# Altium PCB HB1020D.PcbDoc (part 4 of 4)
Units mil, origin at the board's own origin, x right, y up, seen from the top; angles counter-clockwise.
Board outline 4729.44 x 3075.9 mil, 2 copper layers (Top Layer, Bottom Layer); 113 components, 129 nets, 454 pads, 503 vias.
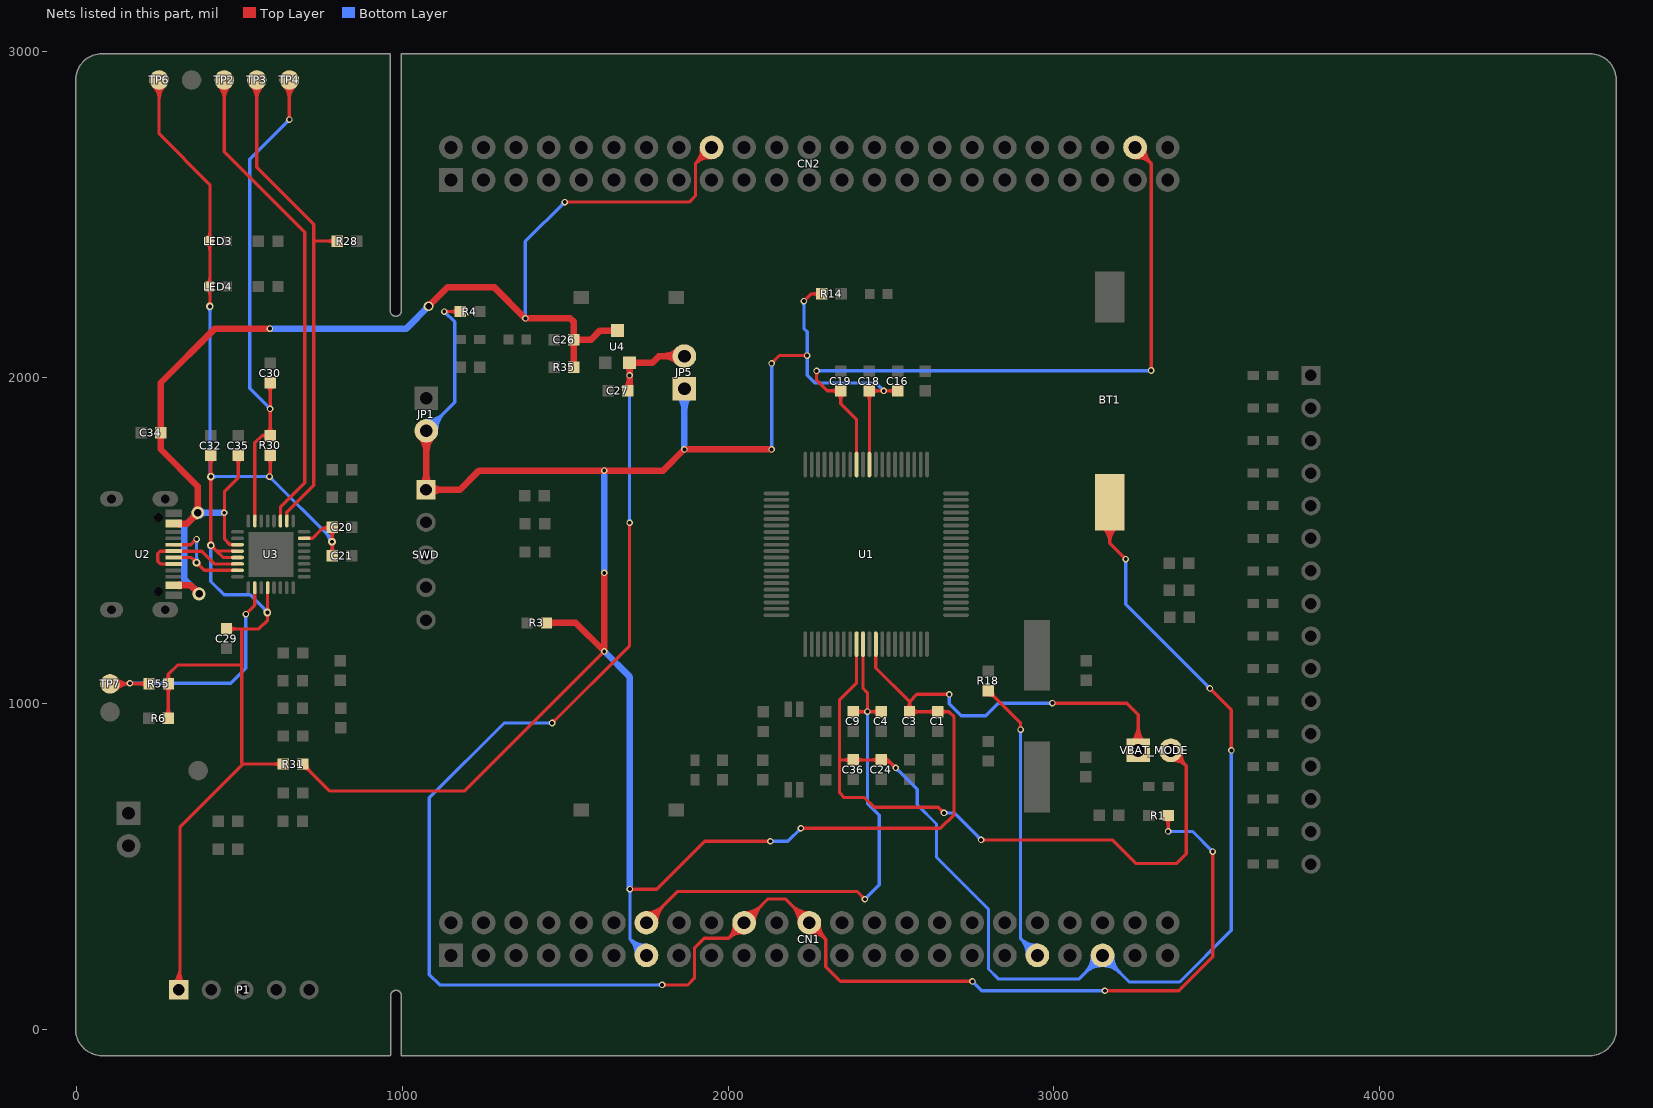
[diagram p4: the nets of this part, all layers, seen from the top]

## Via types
v1: diameter 20, hole 12, Top Layer to Bottom Layer, tented both sides, 475 vias
v2: diameter 23.62, hole 11.81, Top Layer to Bottom Layer, tented both sides, 20 vias
v3: diameter 122.05, hole 122.05, Top Layer to Bottom Layer, tented both sides, 4 vias
v4: diameter 39.37, hole 23.62, Top Layer to Bottom Layer, tented both sides, 2 vias
v5: diameter 30, hole 20, Top Layer to Bottom Layer, tented both sides, 1 vias
v6: diameter 15, hole 8, Top Layer to Bottom Layer, tented both sides, 1 vias

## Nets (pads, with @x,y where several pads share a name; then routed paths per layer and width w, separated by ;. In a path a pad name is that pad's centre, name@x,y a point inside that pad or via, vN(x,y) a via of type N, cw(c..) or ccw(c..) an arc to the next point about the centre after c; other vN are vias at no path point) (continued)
PF1: CN1.37 R18.2 | length 1152.3
  Top Layer w10: R18.2@2798.61,1026.81 cw(c2798.61,996.63) 2819.95,1017.97 cw(c2841.28,1039.31) R18.2@2811.11,1039.31 ; R18.2@2798.61,1039.31 2898,939.91 v1(2898,919.81) ; v1@2894.46,923.35 ccw(c2885.93,931.88) 2898,931.88 ccw(c2910.07,931.88) v1@2901.54,923.35
  Bottom Layer w10: v1@2894.46,916.28 cw(c2885.93,907.74) 2898,907.74 cw(c2910.07,907.74) v1@2901.54,916.28 ; v1@2900.19,922 v1(2898,919.81) 2898,278.39 ; CN1.37@2918.2,227.66 ccw(c2849.18,229.57) 2898,278.39 ; CN1.37@2928.2,227.38 ccw(c2881.14,228.68) 2914.43,261.97 ccw(c2947.71,295.25) CN1.37@2949.01,248.2 ; CN1.37@2948.74,258.19 cw(c2946.83,327.22) 2898,278.39 ; CN1.37@2949.61,226.79 2898,278.39
PF2: C19.2 CN2.44 U1.52 | length 2435.9
  Top Layer w10: v1@2268.46,2017.46 cw(c2259.93,2008.93) 2272,2008.93 cw(c2284.07,2008.93) v1@2275.54,2017.46 ; v1(2272,2021) 2272,1992 2304.21,1959.79 C19.2@2346.27,1959.79 2346.27,1919.73 2394.74,1871.26 U1.52@2394.74,1733.38 ; C19.2@2337.43,1968.63 cw(c2316.09,1989.97) 2316.09,1959.79 cw(c2316.09,1929.61) 2337.43,1950.95 cw(c2316.09,1929.61) 2346.27,1929.61 cw(c2376.44,1929.61) C19.2@2355.11,1950.95 ; CN2.44@3249.61,2706.79 3299.02,2657.37 ; CN2.44@3250.88,2685.41 cw(c3253.4,2643.21) 3283.29,2673.1 cw(c3313.19,2702.99) CN2.44@3270.99,2705.51 ; CN2.44@3251.48,2675.43 cw(c3255.17,2613.52) 3299.02,2657.37 ; CN2.44@3280.97,2704.92 ccw(c3342.87,2701.22) 3299.02,2657.37 ; v1@3295.49,2025.54 ccw(c3286.95,2034.08) 3299.02,2034.08 ccw(c3311.1,2034.08) v1@3302.56,2025.54 ; v1(3299.02,2022.01) 3299.02,2657.37
  Bottom Layer w10: v1(2272,2021) 2352,2021 3298.02,2021 v1(3299.02,2022.01) ; v1@2275.54,2017.46 cw(c2284.07,2008.93) 2284.07,2021 cw(c2284.07,2033.07) v1@2275.54,2024.54 ; 3284.52,2021 ccw(c3284.52,2036.51) v1@3295.49,2025.54
PRG_NRST: C30.1 R30.2 TP4.1 U3.7 | length 1920.5
  Top Layer w10: U3.7@547.39,1560.15 547.39,1800.09 569.61,1822.31 ; R30.2@584.61,1814.81 ccw(c569.61,1803.56) 569.61,1822.31 ; R30.2@584.61,1829.81 cw(c569.61,1841.05) 569.61,1822.31 ; R30.2@585.77,1831.14 ccw(c564.43,1852.48) 594.61,1852.48 ccw(c624.78,1852.48) R30.2@603.45,1831.14 ; C30.1@585.77,1975.47 cw(c564.43,1954.13) 594.61,1954.13 cw(c624.78,1954.13) C30.1@603.45,1975.47 ; v1@591.07,1900.77 cw(c582.54,1892.24) 594.61,1892.24 cw(c606.68,1892.24) v1@598.14,1900.77 ; v1@591.07,1907.84 ccw(c582.54,1916.38) 594.61,1916.38 ccw(c606.68,1916.38) v1@598.14,1907.84 ; C30.1@594.61,1984.31 v1(594.61,1904.31) R30.2@594.61,1822.31 569.61,1822.31 ; TP4.1@635.93,2896.11 cw(c593.25,2853.43) 653.61,2853.43 cw(c713.96,2853.43) TP4.1@671.28,2896.11 ; TP4.1@643,2903.18 cw(c617.39,2877.57) 653.61,2877.57 cw(c689.82,2877.57) TP4.1@664.21,2903.18 ; v1@650.07,2795.84 ccw(c641.54,2804.38) 653.61,2804.38 ccw(c665.68,2804.38) v1@657.14,2795.84 ; v1(653.61,2792.31) TP4.1@653.61,2913.79
  Bottom Layer w10: v1@589.61,1904.31 ccw(c577.54,1904.31) 586.07,1912.84 ccw(c594.61,1921.38) v1@594.61,1909.31 ; v1(594.61,1904.31) 531.61,1967.31 531.61,2670.31 v1(653.61,2792.31) ; v1@648.61,2792.31 cw(c636.54,2792.31) 645.07,2783.77 cw(c653.61,2775.24) v1@653.61,2787.31
PRG_SWCLK: R28.2 TP3.1 U3.2 | length 1731.5
  Top Layer w10: TP3.1@535.93,2896.11 cw(c493.25,2853.43) 553.61,2853.43 cw(c613.96,2853.43) TP3.1@571.28,2896.11 ; TP3.1@543,2903.18 cw(c517.39,2877.57) 553.61,2877.57 cw(c589.82,2877.57) TP3.1@564.21,2903.18 ; TP3.1@553.61,2913.79 553.61,2645.31 728.61,2470.31 728.61,1669.31 645.82,1586.52 U3.2@645.82,1560.15 ; 728.61,2419.31 R28.2@800.61,2419.31 ; R28.2@791.77,2410.47 ccw(c770.43,2389.13) 770.43,2419.31 ccw(c770.43,2449.49) R28.2@791.77,2428.15
PRG_SWDIO: TP2.1 U3.3 | length 1640.5
  Top Layer w10: TP2.1@435.93,2896.11 cw(c393.25,2853.43) 453.61,2853.43 cw(c513.96,2853.43) TP2.1@471.28,2896.11 ; TP2.1@443,2903.18 cw(c417.39,2877.57) 453.61,2877.57 cw(c489.82,2877.57) TP2.1@464.21,2903.18 ; TP2.1@453.61,2913.79 453.61,2693.31 700.61,2446.31 700.61,1677.31 626.13,1602.83 U3.3@626.13,1560.15 U3.3@626.13,1558.18
UPDATE_CTRL: R55.2 TP7.1 U3.18 | length 1036.9
  Top Layer w10: TP7.1@103.35,1060.31 R55.2@222.61,1060.31 ; TP7.1@113.65,1049.39 cw(c140,1023.04) 140,1060.31 ; TP7.1@113.65,1070.61 ccw(c138.51,1095.47) 138.51,1060.31 ; TP7.1@120.72,1042.32 cw(c164.14,998.9) v1@164.14,1060.31 ; TP7.1@120.72,1077.68 ccw(c162.65,1119.61) v1@162.65,1060.31 ; 147.84,1060.31 ccw(c147.84,1078.16) v1@160.46,1065.54 ; v1@167.54,1065.54 ccw(c180.16,1078.16) 180.16,1060.31 ; R55.2@213.77,1051.47 ccw(c192.43,1030.13) 192.43,1060.31 ccw(c192.43,1090.49) R55.2@213.77,1069.15 ; v1(520,1274) 547.39,1301.39 U3.18@547.39,1355.43 ; v1@520,1279 ccw(c520,1291.07) 528.54,1282.54 ccw(c537.07,1274) v1@525,1274
  Bottom Layer w10: v1(164,1062) 473.61,1062 520,1108.39 v1(520,1274) ; v1@167.54,1058.46 cw(c176.07,1049.93) 176.07,1062 cw(c176.07,1074.07) v1@167.54,1065.54 ; v1@516.46,1270.46 cw(c507.93,1261.93) 520,1261.93 cw(c532.07,1261.93) v1@523.54,1270.46
USB_DM: U2.A7 U2.B7 U3.15 | length 479.4
  Top Layer w10: U2.A7@298.2,1447.87 353.04,1447.87 392.34,1408.57 U3.15@494.24,1408.57 U3.15@496.21,1408.57 ; U2.B7@298.2,1487.24 351.54,1487.24 v1(368.61,1504.31) ; v2@361.93,1432.17 ccw(c345.49,1432.17) 357.12,1443.8 ccw(c368.74,1455.42) v2@368.74,1438.98 ; v1@363.61,1504.31 cw(c351.54,1504.31) 360.07,1495.77 cw(c368.61,1487.24) v1@368.61,1499.31 ; v2@368.74,1425.36 cw(c368.74,1408.92) 380.37,1420.54 cw(c392,1432.17) v2@375.56,1432.17
  Bottom Layer w10: v2@363.93,1436.99 ccw(c352.3,1448.61) 368.74,1448.61 ccw(c385.19,1448.61) v2@373.56,1436.99 ; v1@365.07,1500.77 cw(c356.2,1491.9) 368.74,1491.9 ; v1(368.61,1504.31) 368.74,1504.17 v2(368.74,1432.17) ; 368.74,1492.57 cw(c380.34,1492.57) v1@372.14,1500.77
USB_DP: U2.A6 U2.B6 U3.14 | length 341.8
  Top Layer w10: U2.B6@298.2,1428.18 257.73,1428.18 249.61,1436.31 249.61,1460.31 256.85,1467.55 U2.A6@298.2,1467.55 384.36,1467.55 384.61,1467.31 423.65,1428.26 U3.14@494.24,1428.26 U3.14@496.21,1428.26
VBAT: BT1.1 C24.2 C36.2 CN1.41 U1.9 VBAT_MODE.2 | length 6533.9
  Top Layer w10: 2342.69,826.79 C36.2@2384.6,826.79 C24.2@2470.93,826.79 2490.21,826.79 ; C36.2@2375.76,817.95 ccw(c2354.42,796.61) 2354.42,826.79 ccw(c2354.42,856.96) C36.2@2375.76,835.62 ; C36.2@2393.44,817.95 cw(c2414.78,796.61) 2414.78,826.79 cw(c2414.78,856.96) C36.2@2393.44,835.62 ; U1.9@2394.74,1182.2 2394.74,1063.74 2342.48,1011.48 2342.48,725.52 2357,711 2419,711 2449,681 2646,681 v1(2663,664) ; C24.2@2462.1,817.95 ccw(c2440.76,796.61) 2440.76,826.79 ccw(c2440.76,856.96) C24.2@2462.1,835.62 ; C24.2@2470.87,834.29 cw(c2471.11,806.28) 2490.91,826.09 ; C24.2@2470.96,824.29 cw(c2471.41,772.86) 2507.78,809.22 ; C24.2@2472.63,824.94 cw(c2482.33,814.38) 2492.48,824.52 ; C24.2@2479.39,817.58 cw(c2489.4,806.69) 2499.85,817.15 ; C24.2@2482.35,821.69 cw(c2490.21,818.17) 2490.21,826.79 ; C24.2@2482.35,831.89 ccw(c2490.21,835.4) 2490.21,826.79 ; v1@2510,802 ccw(c2497.93,802) 2506.46,810.54 ccw(c2515,819.07) v1@2515,807 ; v1(2515,802) 2490.21,826.79 ; v1@2658,664 ccw(c2645.93,664) 2654.46,672.54 ccw(c2663,681.07) v1@2663,669 ; v1(2777,581) 3178.95,581 3250.95,509 3377.6,509 3407,538.4 3407,808 ; v1@2780.54,577.46 cw(c2789.07,568.93) 2789.07,581 cw(c2789.07,593.07) v1@2780.54,584.54 ; BT1.1@3146.37,1545.06 cw(c3104.04,1492.4) 3171.61,1492.4 ; BT1.1@3152.64,1552.85 cw(c3120.82,1513.27) 3171.61,1513.27 cw(c3222.4,1513.27) BT1.1@3190.58,1552.85 ; BT1.1@3171.61,1617.79 3171.61,1492.39 ; BT1.1@3196.84,1545.06 ccw(c3239.17,1492.4) 3171.61,1492.4 ; v1@3216,1443 ccw(c3203.93,1443) 3212.46,1451.54 ccw(c3221,1460.07) v1@3221,1448 ; v1(3221,1443) 3171.61,1492.39 ; VBAT_MODE.2@3359,856 3407,808 ; VBAT_MODE.2@3360.74,834.65 cw(c3363.95,795.5) 3391.72,823.28 cw(c3419.5,851.06) VBAT_MODE.2@3380.35,854.26 ; VBAT_MODE.2@3361.56,824.69 cw(c3366.25,767.26) 3407,808 ; VBAT_MODE.2@3390.31,853.44 ccw(c3447.74,848.75) 3407,808 ; v1@3479,1041 cw(c3479,1028.93) 3487.54,1037.46 cw(c3496.07,1046) v1@3484,1046 ; v1(3479,1046) 3545,980 v1(3545,856) ; v1@3541.46,859.54 ccw(c3532.93,868.07) 3545,868.07 ccw(c3557.07,868.07) v1@3548.54,859.54
  Bottom Layer w10: v1@2515,797 cw(c2515,784.93) 2523.54,793.46 cw(c2532.07,802) v1@2520,802 ; v1(2515,802) 2581,736 2581,689 2640,630 2640,528 2799.65,368.35 2799.65,184.87 2830.52,154 3076.82,154 CN1.41@3149.61,226.79 3231.39,145 3386.16,145 3545,303.84 v1(3545,856) ; v1(2663,664) 2694,664 v1(2777,581) ; v1@2666.54,660.46 cw(c2675.07,651.93) 2675.07,664 cw(c2675.07,676.07) v1@2666.54,667.54 ; v1@2772,581 ccw(c2759.93,581) 2768.46,589.54 ccw(c2777,598.07) v1@2777,586 ; CN1.41@3118.19,226.79 cw(c3042.34,226.79) 3095.97,173.16 cw(c3149.61,119.52) 3149.61,195.37 cw(c3149.61,119.52) 3203.24,173.16 cw(c3256.87,226.79) CN1.41@3181.02,226.79 ; CN1.41@3128.19,226.79 cw(c3076.48,226.79) 3113.04,190.23 cw(c3149.61,153.66) 3149.61,205.37 cw(c3149.61,153.66) 3186.17,190.23 cw(c3222.73,226.79) CN1.41@3171.02,226.79 ; v1@3217.46,1439.46 cw(c3208.93,1430.93) 3221,1430.93 cw(c3233.07,1430.93) v1@3224.54,1439.46 ; v1(3221,1443) 3221,1304 v1(3479,1046) ; v1@3474,1046 ccw(c3461.93,1046) 3470.46,1054.54 ccw(c3479,1063.07) v1@3479,1051 ; v1@3541.46,852.46 cw(c3532.93,843.93) 3545,843.93 cw(c3557.07,843.93) v1@3548.54,852.46
VBUS_5V: C26.2 C34.2 C35.1 CN2.18 R35.2 U2.A4 U2.A9 U2.B4 U2.B9 U3.11 U4.3 | length 4839.7
  Top Layer w10: v1@450.07,1581.77 cw(c439.12,1570.82) 454.61,1570.82 ; v1@450.07,1588.84 ccw(c439.12,1599.79) 454.61,1599.79 ; 454.61,1538.79 454.61,1518.79 ; 463.85,1494.55 ccw(c480.07,1510.77) U3.11@480.07,1487.83 ; C35.1@487.77,1752.95 cw(c466.43,1731.61) 496.61,1731.61 cw(c526.78,1731.61) C35.1@505.45,1752.95 ; U3.11@496.21,1486.63 U3.11@504.21,1486.63 ; U3.11@496.21,1487.31 U3.11@494.24,1487.31 471.08,1487.31 454.61,1503.79 454.61,1518.79 ; C35.1@496.61,1761.79 496.61,1693.31 454.61,1651.31 454.61,1518.79 ; v1(1498.91,2539) 1880.48,2539 1900.19,2558.71 1900.19,2657.37 ; v1@1502.45,2535.46 cw(c1510.98,2526.93) 1510.98,2539 cw(c1510.98,2551.07) v1@1502.45,2542.54 ; CN2.18@1918.24,2704.92 cw(c1856.34,2701.22) 1900.19,2657.37 ; CN2.18@1928.23,2705.51 cw(c1886.03,2702.99) 1915.92,2673.1 cw(c1945.81,2643.21) CN2.18@1948.33,2685.41 ; CN2.18@1947.74,2675.43 ccw(c1944.04,2613.52) 1900.19,2657.37 ; CN2.18@1949.61,2706.79 1900.19,2657.37
  Top Layer w20: C34.2@253.3,1825.48 cw(c240.5,1812.68) 258.61,1812.68 cw(c276.71,1812.68) C34.2@263.91,1825.48 ; C34.2@253.3,1836.09 ccw(c240.5,1848.89) 258.61,1848.89 ccw(c276.71,1848.89) C34.2@263.91,1836.09 ; U2.B9@286.61,1552.19 340.49,1552.19 372.61,1584.31 v4(372.61,1585.31) 372.61,1666.31 258.61,1780.31 C34.2@258.61,1830.79 258.61,1984.31 425.09,2150.79 v1(593.61,2150.79) ; U2.A9@298.2,1363.21 349.7,1363.21 v4(376.61,1336.31) ; U2.A9@314.99,1360.21 cw(c322.24,1352.95) U2.A9@322.24,1363.21 ; U2.B4@314.99,1366.23 ccw(c322.28,1373.53) U2.A9@322.28,1363.21 ; U2.B9@315,1549.19 cw(c322.26,1541.93) U2.B9@322.26,1552.19 ; U2.A4@315,1555.2 ccw(c322.27,1562.48) U2.B9@322.27,1552.19 ; 355.37,1567.07 ccw(c337.13,1585.31) v4@362.92,1585.31 ; 357.78,1569.48 cw(c372.61,1554.66) v4@372.61,1575.62 ; v4@365.76,1592.16 ccw(c349.22,1608.69) 372.61,1608.69 ccw(c395.99,1608.69) v4@379.45,1592.16 ; v4@366.92,1336.31 ccw(c343.54,1336.31) 360.07,1352.84 ccw(c376.61,1369.37) v4@376.61,1345.99 ; v5(1081,2219) 1140,2278 1282,2278 v1(1378,2182) 1516,2182 1527,2171 C26.2@1527,2117 ; R35.2@1521.7,2037.3 ccw(c1508.89,2050.11) 1527,2050.11 ccw(c1545.11,2050.11) R35.2@1532.3,2037.3 ; C26.2@1521.7,2111.7 cw(c1508.89,2098.89) 1527,2098.89 cw(c1545.11,2098.89) 1532.3,2111.7 cw(c1545.11,2098.89) 1545.11,2117 cw(c1545.11,2135.11) 1532.3,2122.3 cw(c1545.11,2135.11) 1527,2135.11 cw(c1508.89,2135.11) C26.2@1521.7,2122.3 ; R35.2@1527,2032 C26.2@1527,2117 ; U4.3@1653.55,2137.58 ccw(c1637.02,2121.04) 1637.02,2144.42 ccw(c1637.02,2167.81) U4.3@1653.55,2151.27 ; U4.3@1660.4,2144.42 1607.42,2144.42 1580,2117 C26.2@1527,2117
  Bottom Layer w10: v1@1374.46,2185.54 ccw(c1365.93,2194.07) 1378,2194.07 ccw(c1390.07,2194.07) v1@1381.54,2185.54 ; v1(1378,2182) 1378,2418.09 v1(1498.91,2539) ; v1@1493.91,2539 cw(c1481.84,2539) 1490.37,2530.46 cw(c1498.91,2521.93) v1@1498.91,2534
  Bottom Layer w20: v4@362.92,1585.31 cw(c339.54,1585.31) 356.07,1568.77 cw(c372.61,1552.24) v4@372.61,1575.62 ; v4@366.92,1336.31 ccw(c343.54,1336.31) 360.07,1352.84 ccw(c376.61,1369.37) v4@376.61,1345.99 ; v4(376.61,1336.31) 331.61,1381.31 331.61,1544.31 v4(372.61,1585.31) v1(453.61,1585.31) ; v4@379.45,1578.46 cw(c395.99,1561.93) 395.99,1585.31 cw(c395.99,1608.69) v4@379.45,1592.16 ; v1(593.61,2150.79) 1012.79,2150.79 v5(1081,2219)
VCORE: C4.1 C9.1 CN1.14 U1.10 | length 2037.4
  Top Layer w10: CN1.14@1749.61,326.79 1845.82,423 2396,423 v1(2420,399) ; CN1.14@1749.61,348.21 ccw(c1749.61,399.91) 1786.17,363.35 ccw(c1822.73,326.79) CN1.14@1771.02,326.79 ; CN1.14@1749.61,358.21 ccw(c1749.61,434.05) 1803.24,380.42 ccw(c1856.87,326.79) CN1.14@1781.02,326.79 ; C9.1@2384.6,974.79 v1(2428,974.79) ; C9.1@2393.44,965.95 cw(c2414.78,944.61) 2414.78,974.79 cw(c2414.78,1004.97) C9.1@2393.44,983.63 ; U1.10@2414.42,1182.2 2414.42,1046.57 2428,1033 v1(2428,974.79) ; v1@2415,399 ccw(c2402.93,399) 2411.46,407.54 ccw(c2420,416.07) v1@2420,404 ; v1@2424.46,971.25 ccw(c2415.93,962.72) 2415.93,974.79 ccw(c2415.93,986.86) 2424.46,978.32 ccw(c2415.93,986.86) 2428,986.86 ccw(c2440.07,986.86) 2431.54,978.32 ccw(c2440.07,986.86) 2440.07,974.79 ccw(c2440.07,962.72) v1@2431.54,971.25 ; C4.1@2462.1,965.95 ccw(c2440.76,944.61) 2440.76,974.79 ccw(c2440.76,1004.97) C4.1@2462.1,983.63 ; C4.1@2470.93,974.79 v1(2428,974.79)
  Bottom Layer w10: v1(2420,399) 2464,443 2464,656.9 2428,692.9 v1(2428,974.79) ; v1@2420,404 ccw(c2420,416.07) 2428.54,407.54 ccw(c2437.07,399) v1@2425,399 ; v1@2424.46,971.25 cw(c2415.93,962.72) 2428,962.72 cw(c2440.07,962.72) v1@2431.54,971.25
VDD: C1.2 C3.2 C16.1 C18.1 CN1.13 JP1.2 JP5.1 R3.1 R4.2 R14.2 R31.2 SWD.1 U1.12 U1.50 VBAT_MODE.1 | length 10650.4
  Top Layer w10: R31.2@695,801.5 cw(c695,771.32) 716.34,792.66 cw(c737.68,814) R31.2@707.5,814 ; R31.2@695,814 778,731 1191,731 v1(1620,1160) ; v1(1129,2203) R4.2@1178,2203 ; v1@1132.54,2199.47 cw(c1141.07,2190.93) 1141.07,2203 cw(c1141.07,2215.07) v1@1132.54,2206.54 ; R4.2@1169.16,2194.16 ccw(c1147.82,2172.82) 1147.82,2203 ccw(c1147.82,2233.18) R4.2@1169.16,2211.84 ; v1@1615,1160 cw(c1602.93,1160) 1611.46,1151.46 cw(c1620,1142.93) v1@1620,1155 ; v1(1699.02,430) 1781,430 1928,577 v1(2130,577) ; v1@1702.56,426.46 cw(c1711.1,417.93) 1711.1,430 cw(c1711.1,442.07) v1@1702.56,433.54 ; v1@2126.46,573.46 ccw(c2117.93,564.93) 2117.93,577 ccw(c2117.93,589.07) v1@2126.46,580.54 ; v1(2134,2044) 2158,2068 v1(2243,2068) ; v1@2134,2049 ccw(c2134,2061.07) 2142.54,2052.54 ccw(c2151.07,2044) v1@2139,2044 ; v1(2224,617) 2652,617 2694,659 2694,958.6 2677.81,974.79 C1.2@2643.6,974.79 2557.27,974.79 2557.27,1005.34 ; v1@2227.54,613.46 cw(c2236.07,604.93) 2236.07,617 cw(c2236.07,629.07) v1@2227.54,620.54 ; v1(2233,2235) 2255,2257 R14.2@2288,2257 ; v1@2233,2240 ccw(c2233,2252.07) 2241.54,2243.54 ccw(c2250.07,2235) v1@2238,2235 ; v1@2239.46,2064.46 ccw(c2230.93,2055.93) 2230.93,2068 ccw(c2230.93,2080.07) v1@2239.46,2071.54 ; R14.2@2279.16,2248.16 ccw(c2257.82,2226.82) 2257.82,2257 ccw(c2257.82,2287.18) R14.2@2279.16,2265.84 ; C18.1@2424.77,1950.95 cw(c2402.21,1928.39) 2434.11,1928.39 ; U1.50@2434.11,1733.38 2434.11,1959.29 v1(2478,1959.29) C16.1@2521.1,1959.29 ; 2434.11,1930.83 cw(c2462.57,1930.83) 2442.45,1950.95 cw(c2462.57,1930.82) 2462.57,1959.29 ; C18.1@2442.45,1968.63 ccw(c2465,1991.18) 2465,1959.29 ; U1.12@2453.79,1182.2 2453.79,1108.81 2557.27,1005.34 ; v1@2474.46,1955.75 ccw(c2465.93,1947.21) 2465.93,1959.29 ccw(c2465.93,1971.36) v1@2474.46,1962.82 ; v1@2481.54,1955.75 cw(c2490.07,1947.21) 2490.07,1959.29 cw(c2490.07,1971.36) v1@2481.54,1962.82 ; 2490.22,1959.29 ccw(c2490.22,1991.18) C16.1@2512.77,1968.63 ; 2492.64,1959.29 cw(c2492.64,1930.82) C16.1@2512.77,1950.95 ; C3.2@2548.43,983.84 ccw(c2527.1,1005.17) 2557.27,1005.17 ; 2557.27,1005.18 ccw(c2587.46,1005.18) 2566.11,983.84 ccw(c2587.96,1005.68) 2587.96,974.79 ; C3.2@2566.11,966.16 cw(c2586.94,945.33) 2586.94,974.79 ; C1.2@2634.76,965.95 ccw(c2613.42,944.61) 2613.42,974.79 ccw(c2613.43,1004.96) C1.2@2634.76,983.63 ; C1.2@2652.44,965.95 cw(c2673.78,944.61) 2673.78,974.79 cw(c2673.78,1004.96) C1.2@2652.44,983.63 ; v1@2675.46,1024.46 ccw(c2666.93,1015.93) 2666.93,1028 ccw(c2666.93,1040.07) v1@2675.46,1031.54 ; v1(2679,1028) 2579.93,1028 2557.27,1005.34 ; v1(2996,1001) 3224,1001 3259,966 VBAT_MODE.1@3259,856 ; v1@2999.54,997.46 cw(c3008.07,988.93) 3008.07,1001 cw(c3008.07,1013.07) v1@2999.54,1004.54 ; VBAT_MODE.1@3236.78,878.22 ccw(c3183.15,931.85) 3259,931.85 ccw(c3334.85,931.85) VBAT_MODE.1@3281.22,878.22 ; VBAT_MODE.1@3243.86,871.14 ccw(c3207.29,907.71) 3259,907.71 ccw(c3310.71,907.71) VBAT_MODE.1@3274.14,871.14
  Top Layer w20: JP1.2@1055.32,1818.32 cw(c1010.22,1773.22) 1074,1773.22 cw(c1137.78,1773.22) JP1.2@1092.68,1818.32 ; SWD.1@1059.19,1669.81 ccw(c1023.44,1705.56) 1074,1705.56 ; SWD.1@1073,1656 1177,1656 1236,1715 v1(1620,1715) 1801,1715 v1(1866,1780) v1(2134,1780) ; SWD.1@1074,1657 JP1.2@1074,1837 ; 1074,1700.73 ccw(c1117.73,1700.73) 1086.81,1669.81 ccw(c1120.14,1703.14) 1120.14,1656 ccw(c1120.14,1608.86) SWD.1@1086.81,1642.19 ; R3.1@1443,1247 1533,1247 v1(1620,1160) v1(1620,1401) ; R3.1@1448.3,1241.7 cw(c1461.11,1228.89) 1461.11,1247 cw(c1461.11,1265.11) R3.1@1448.3,1252.3
  Bottom Layer w10: JP1.2@1074,1837 1161,1924 1161,2171 v1(1129,2203) ; JP1.2@1074,1858.42 ccw(c1074,1910.12) 1110.56,1873.56 ccw(c1147.12,1837) JP1.2@1095.42,1837 ; JP1.2@1074,1868.42 ccw(c1074,1944.27) 1127.63,1890.63 ccw(c1181.26,1837) JP1.2@1105.42,1837 ; v1@1129,2198 cw(c1129,2185.93) 1137.54,2194.47 cw(c1146.07,2203) v1@1134,2203 ; v1@1695.49,426.46 cw(c1686.95,417.93) 1699.02,417.93 cw(c1711.1,417.93) v1@1702.56,426.46 ; v1(1699.02,430) 1699.02,277.37 ; CN1.13@1718.22,228.12 ccw(c1652.56,230.9) 1699.03,277.37 ; CN1.13@1728.21,227.69 ccw(c1683.45,229.59) 1715.13,261.27 ccw(c1746.81,292.95) CN1.13@1748.7,248.19 ; CN1.13@1748.28,258.18 cw(c1745.5,323.84) 1699.03,277.37 ; CN1.13@1749.61,226.79 1699.02,277.37 ; v1(2130,577) 2184,577 v1(2224,617) ; v1@2130.46,1783.54 ccw(c2121.93,1792.07) 2134,1792.07 ccw(c2146.07,1792.07) v1@2137.54,1783.54 ; v1@2130.46,2040.46 cw(c2121.93,2031.93) 2134,2031.93 cw(c2146.07,2031.93) v1@2137.54,2040.46 ; v1@2133.54,573.46 cw(c2142.07,564.93) 2142.07,577 cw(c2142.07,589.07) v1@2133.54,580.54 ; v1(2134,1780) v1(2134,2044) ; v1@2219,617 cw(c2206.93,617) 2215.46,608.46 cw(c2224,599.93) v1@2224,612 ; v1@2229.46,2231.46 cw(c2220.93,2222.93) 2233,2222.93 cw(c2245.07,2222.93) v1@2236.54,2231.46 ; v1(2233,2235) 2233,2151 2243,2141 v1(2243,2068) 2243,2007 2266,1984 2453.28,1984 v1(2478,1959.29) ; v1@2239.46,2064.46 cw(c2230.93,2055.93) 2243,2055.93 cw(c2255.07,2055.93) v1@2246.54,2064.46 ; v1@2239.46,2071.54 ccw(c2230.93,2080.07) 2243,2080.07 ccw(c2255.07,2080.07) v1@2246.54,2071.54 ; v1@2473,1959.29 ccw(c2460.93,1959.29) 2469.46,1967.82 ccw(c2478,1976.36) v1@2478,1964.29 ; v1@2675.46,1024.46 cw(c2666.93,1015.93) 2679,1015.93 cw(c2691.07,1015.93) v1@2682.54,1024.46 ; v1(2679,1028) 2679,999 2716,962 2791,962 2830,1001 v1(2996,1001) ; v1@2992.46,997.46 ccw(c2983.93,988.93) 2983.93,1001 ccw(c2983.93,1013.07) v1@2992.46,1004.54
  Bottom Layer w20: v1(1620,1160) 1699.02,1080.98 v1(1699.02,430) ; v1(1620,1401) v1(1620,1715) ; JP5.1@1847.32,1947.32 cw(c1802.22,1902.22) 1866,1902.22 cw(c1929.78,1902.22) JP5.1@1884.68,1947.32 ; v1(1866,1780) JP5.1@1866,1966
VDD_LINK: C20.2 C21.2 C29.2 C32.1 LED3.1 LED4.1 P1.1 R6.2 R30.1 R31.1 R55.1 TP6.1 U3.12 U3.13 U3.20 U3.31 | length 6019.7
  Top Layer w10: TP6.1@235.93,2896.11 cw(c193.25,2853.43) 253.61,2853.43 cw(c313.96,2853.43) TP6.1@271.28,2896.11 ; TP6.1@243,2903.18 cw(c217.39,2877.57) 253.61,2877.57 cw(c289.82,2877.57) TP6.1@264.21,2903.18 ; TP6.1@253.61,2913.79 253.61,2748.31 409.61,2592.31 409.61,2419.31 v2(409.61,2218.79) ; R6.2@273.16,963.84 ccw(c251.82,985.18) 282,985.18 ccw(c312.18,985.18) R6.2@290.84,963.84 ; R55.1@273.77,1051.47 cw(c253.89,1031.59) 282,1031.59 ; R55.1@273.77,1069.15 ccw(c253.89,1089.02) 282,1089.02 ; R6.2@282,955 282,1089.31 ; 282,1028.67 cw(c314.25,1028.67) R55.1@291.45,1051.47 ; R55.1@290.87,1069.69 cw(c308.13,1089.31) 282,1089.31 ; P1.1@296.66,138.34 ccw(c245.13,189.87) 318,189.87 ; P1.1@303.73,131.27 ccw(c269.27,165.73) 318,165.73 ; P1.1@318,125 318,621 511,814 ; 318,170.56 ccw(c363.56,170.56) P1.1@331.34,138.34 ; LED4.1@400.54,2272.72 cw(c378.64,2250.82) 409.61,2250.82 ; LED4.1@400.54,2286.86 ccw(c378.64,2308.76) 409.61,2308.76 ; LED3.1@400.54,2412.24 cw(c378.64,2390.34) 409.61,2390.34 ; LED3.1@400.54,2426.38 ccw(c378.64,2448.28) 409.61,2448.28 ; C32.1@403.77,1752.95 cw(c382.43,1731.61) 412.61,1731.61 cw(c442.78,1731.61) C32.1@421.45,1752.95 ; v2@404.79,2223.6 ccw(c393.16,2235.23) 409.61,2235.23 ccw(c426.05,2235.23) v2@414.42,2223.6 ; v2@407.79,1490.12 ccw(c396.16,1501.75) 412.61,1501.75 ccw(c429.05,1501.75) v2@417.42,1490.12 ; v2@407.79,1691.49 cw(c396.16,1679.86) 412.61,1679.86 cw(c429.05,1679.86) v2@417.42,1691.49 ; v2@407.79,1701.12 ccw(c396.16,1712.75) 412.61,1712.75 ccw(c429.05,1712.75) v2@417.42,1701.12 ; 409.61,2260.47 cw(c426.92,2260.47) LED4.1@414.68,2272.72 ; 409.61,2299.1 ccw(c426.92,2299.1) LED4.1@414.68,2286.86 ; 409.61,2399.99 cw(c426.92,2399.99) LED3.1@414.68,2412.24 ; 409.61,2438.62 ccw(c426.92,2438.62) LED3.1@414.68,2426.38 ; v2@412.61,1478.49 cw(c412.61,1462.05) 424.23,1473.68 cw(c435.86,1485.31) v2@419.42,1485.31 ; C32.1@412.61,1761.79 v2(412.61,1696.31) v2(412.61,1485.31) 430.28,1467.63 ; C29.2@460.61,1228.79 507.61,1228.79 ; C29.2@469.45,1219.95 cw(c490.78,1198.61) 490.78,1228.79 cw(c490.78,1258.96) C29.2@469.45,1237.62 ; U3.12@494.24,1467.63 430.28,1467.63 ; U3.13@496.21,1447.94 U3.13@494.24,1447.94 449.97,1447.94 430.28,1467.63 ; v2@581.18,1274.18 cw(c567.71,1260.71) 586.76,1260.71 ; v2@581.18,1283.82 ccw(c568.65,1296.35) 586.38,1296.35 ; R30.1@585.77,1753.47 cw(c564.43,1732.13) 594.61,1732.13 cw(c624.78,1732.13) R30.1@603.45,1753.47 ; 586.38,1294.53 ccw(c601.53,1294.53) v2@590.82,1283.82 ; 586.76,1264.4 cw(c600.6,1264.4) v2@590.82,1274.18 ; U3.20@586.76,1357.39 U3.20@586.76,1355.43 586.38,1355.04 586.38,1289.65 586.76,1289.26 586.76,1255.46 560.09,1228.79 507.61,1228.79 ; v1@589.07,1699.84 ccw(c575.71,1713.2) 594.61,1713.2 ; v1(592.61,1696.31) 594.61,1698.31 R30.1@594.61,1762.31 ; R31.1@626.16,805.16 ccw(c604.82,783.82) 604.82,814 ccw(c604.82,844.18) R31.1@626.16,822.84 ; R31.1@635,814 511,814 ; U3.31@697,1507 U3.31@698.97,1507 724.82,1507 747.61,1529.79 755.61,1537.79 ; 762.67,1537.79 cw(c762.67,1517.85) 776.77,1531.95 cw(c757.84,1513.02) 784.61,1513.02 ; C20.2@775.41,1548.02 cw(c755.61,1562.07) 755.61,1537.79 ; C21.2@776.77,1461.63 ccw(c757.84,1480.55) 784.61,1480.55 ; v2@779.79,1491.49 cw(c768.16,1479.86) 784.61,1479.86 cw(c801.05,1479.86) v2@789.42,1491.49 ; v2@779.79,1501.12 ccw(c768.16,1512.75) 784.61,1512.75 ccw(c801.05,1512.75) v2@789.42,1501.12 ; C21.2@784.61,1447.79 v2(784.61,1496.31) 784.61,1537.79 755.61,1537.79 ; v2@784.61,1485.38 ccw(c818.2,1485.38) C21.2@794.45,1461.63 ; 784.61,1508.2 cw(c818.2,1508.2) C20.2@794.45,1531.95 ; 282,1089.31 310.69,1118 507.61,1118 ; 507.61,1118 507.61,817.39 511,814 ; 507.61,1118 507.61,1228.79
  Bottom Layer w10: v2@404.79,2213.97 cw(c393.16,2202.34) 409.61,2202.34 cw(c426.05,2202.34) v2@414.42,2213.97 ; v2@407.79,1480.49 cw(c396.16,1468.86) 412.61,1468.86 cw(c429.05,1468.86) v2@417.42,1480.49 ; 409.61,1719.99 ccw(c436.29,1719.99) 417.42,1701.12 ccw(c429.05,1712.75) 429.05,1696.31 ccw(c429.05,1679.86) v2@417.42,1691.49 ; v2(409.61,2218.79) 409.61,1699.31 v2(412.61,1696.31) v1(592.61,1696.31) 784.61,1504.31 v2(784.61,1496.31) ; v2(412.61,1485.31) 412.61,1374.31 453.61,1333.31 533.09,1333.31 586.61,1279.79 586,1279.18 v2(586,1279) ; 573.39,1293.01 cw(c559.38,1279) v2@579.19,1279 ; 576.75,1289.64 ccw(c586,1298.89) v2@586,1285.81 ; v1@589.07,1692.77 ccw(c580.54,1684.24) 580.54,1696.31 ccw(c580.54,1708.38) v1@589.07,1699.84 ; v1@592.61,1691.31 cw(c592.61,1679.24) 601.14,1687.77 cw(c609.68,1696.31) v1@597.61,1696.31 ; 767.32,1521.59 cw(c742.04,1496.31) v2@777.8,1496.31
VLDO: C27.2 CN1.20 CN1.24 JP5.2 R1.2 U4.2 | length 7044.4
  Top Layer w10: v1(1460,940) 1697.8,1177.8 v1(1697.8,1554.8) ; v1@1460,945 ccw(c1460,957.07) 1468.54,948.54 ccw(c1477.07,940) v1@1465,940 ; v1@1694.27,1551.27 cw(c1685.73,1542.73) 1697.8,1542.73 cw(c1709.88,1542.73) v1@1701.34,1551.27 ; v1@1799,136 1877.16,136 1897.02,155.86 1897.02,249.21 1927.19,279.37 2002.19,279.37 ; v1@1801.54,132.46 cw(c1810.07,123.93) 1810.07,136 cw(c1810.07,148.07) v1@1801.54,139.54 ; CN1.20@2018.32,323.94 cw(c1962.7,318.87) 2002.19,279.37 ; CN1.20@2028.28,324.84 cw(c1990.36,321.39) 2017.28,294.46 cw(c2044.21,267.54) CN1.20@2047.66,305.46 ; CN1.20@2046.75,295.5 ccw(c2041.68,239.88) 2002.19,279.37 ; CN1.20@2049.61,348.21 ccw(c2049.61,399.91) 2086.17,363.35 ccw(c2122.73,326.79) CN1.20@2071.02,326.79 ; CN1.20@2049.61,358.21 ccw(c2049.61,434.05) 2103.24,380.42 ccw(c2156.87,326.79) CN1.20@2081.02,326.79 ; CN1.24@2218.19,326.79 ccw(c2142.34,326.79) 2195.97,380.42 ccw(c2249.61,434.05) CN1.24@2249.61,358.21 ; CN1.24@2228.19,326.79 ccw(c2176.48,326.79) 2213.04,363.35 ccw(c2249.61,399.91) CN1.24@2249.61,348.21 ; CN1.24@2250.57,305.39 cw(c2252.57,261.05) 2283.96,292.44 cw(c2315.35,323.82) CN1.24@2271,325.82 ; CN1.24@2251.02,295.4 cw(c2253.95,230.35) 2300,276.4 ; CN1.24@2280.99,325.37 ccw(c2346.04,322.44) 2300,276.4 ; v1@2746.46,143.46 ccw(c2737.93,134.93) 2737.93,147 ccw(c2737.93,159.07) v1@2746.46,150.54 ; v1(2750,147) 2345,147 2300,192 2300,276.39 ; v1(3157,118) 3384,118 3488,222 v1(3488,545) ; v1@3160.54,114.46 cw(c3169.07,105.93) 3169.07,118 cw(c3169.07,130.07) v1@3160.54,121.54 ; R1.2@3342.16,647.16 cw(c3320.82,625.82) 3351,625.82 cw(c3381.18,625.82) R1.2@3359.84,647.16 ; v1@3347.46,610.54 ccw(c3338.93,619.07) 3351,619.07 ccw(c3363.07,619.07) v1@3354.54,610.54 ; v1(3351,607) R1.2@3351,656 ; v1@3484.46,541.46 cw(c3475.93,532.93) 3488,532.93 cw(c3500.07,532.93) v1@3491.54,541.46 ; 2002.19,279.37 CN1.20@2049.61,326.79 2122.82,400 2176.39,400 CN1.24@2249.61,326.79 2300,276.39
  Top Layer w20: C27.2@1686.7,1965.3 ccw(c1659.88,1992.12) 1697.8,1992.12 ; U4.2@1690.96,2039.15 cw(c1674.42,2022.62) 1697.8,2022.62 cw(c1721.19,2022.62) 1704.65,2039.15 cw(c1721.19,2022.62) 1721.19,2046 cw(c1721.19,2069.38) U4.2@1704.65,2052.85 ; C27.2@1697.8,1965.8 v1(1697.8,2007) U4.2@1697.8,2046 1768,2046 1788,2066 JP5.2@1866,2066 ; JP5.2@1847.32,2047.32 ccw(c1802.22,2002.22) 1802.22,2066 ccw(c1802.22,2129.78) JP5.2@1847.32,2084.68
  Bottom Layer w10: v1@1456.46,936.46 ccw(c1447.93,927.93) 1447.93,940 ccw(c1447.93,952.07) v1@1456.46,943.54 ; v1(1460,940) 1313,940 1083,710 1083,167.61 1114.61,136 v1(1798,136) ; v1@1694.27,1558.34 ccw(c1685.73,1566.88) 1697.8,1566.88 ccw(c1709.88,1566.88) v1@1701.34,1558.34 ; v1@1694.27,2003.46 cw(c1685.73,1994.93) 1697.8,1994.93 cw(c1709.88,1994.93) v1@1701.34,2003.46 ; v1(1697.8,1554.8) v1(1697.8,2007) ; v1@1794.46,132.46 ccw(c1785.93,123.93) 1785.93,136 ccw(c1785.93,148.07) v1@1794.46,139.54 ; v1@2750,142 cw(c2750,129.93) 2758.54,138.46 cw(c2767.07,147) v1@2755,147 ; v1(2750,147) 2779,118 v1(3157,118) ; v1@3153.46,114.46 ccw(c3144.93,105.93) 3144.93,118 ccw(c3144.93,130.07) v1@3153.46,121.54 ; v1(3351,607) 3426,607 v1(3488,545) ; v1@3354.54,603.46 cw(c3363.07,594.93) 3363.07,607 cw(c3363.07,619.07) v1@3354.54,610.54 ; v1@3483,545 ccw(c3470.93,545) 3479.46,553.54 ccw(c3488,562.07) v1@3488,550
pads on no net: CN1.26 CN1.32 CN2.15 U2. U2.A5 U2.A8 U2.B5 U2.B8 U3.1 U3.4 U3.8 U3.9 U3.10 U3.16 U3.27 U3.28 U3.29 U3.30
copper on no net:
  other v1: 3333,396 3377,397 3331,538
  other v3: 118.11,47.2 4606.3,47.2 118.11,2874.06 4606.3,2874.06

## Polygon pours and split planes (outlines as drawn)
GND on Top Layer "Top Layer-No Net" (solid, remove dead copper, pour order 1000): 80.81,2991.17 32.15,2991.17 5.88,2966 -1.36,2959.06 -1.36,2912.43 -1.36,-0.94 -1.42,-1 -1.42,-35 22.58,-58 45.22,-79.69 80.74,-79.69 4659.8,-79.69 4674.73,-79.69 4706.75,-49 4722.99,-33.44 4722.99,-13.45 4722.99,2945.44 4703.62,2964 4675.27,2991.18 4645.19,2991.18
GND on Bottom Layer "Top Layer-No Net" (solid, remove dead copper, pour order 1001): 81.23,2993.65 32.57,2993.65 6.3,2968.48 -0.94,2961.54 -0.94,2914.91 -0.94,1.54 -1,1.48 -1,-32.52 23,-55.52 45.64,-77.21 81.16,-77.21 4660.22,-77.21 4675.15,-77.21 4707.17,-46.52 4723.41,-30.96 4723.41,-10.97 4723.41,2947.92 4704.04,2966.48 4675.69,2993.65 4645.61,2993.65

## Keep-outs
Keep-Out Layer:
  lines w5: 0,2913.43 0,0.05 ccw(c78.74,0.05) 78.74,-78.69 962,-78.69 962,103 cw(c981,103) 1000,103 ; 0.06,2913.43 cw(c78.8,2913.43) 78.8,2992.17 959.61,2992.17 ; 960.05,2050.24 cw(c979.52,2043.83) 1000.02,2043.71 ; 960.47,1755.05 ccw(c980.45,1758.4) 999.61,1751.79 ; 960.47,2203.05 ccw(c980.45,2206.4) 999.61,2199.79 ; 960.63,1757.79 960.63,2048.79 ; 960.63,1759.51 960.63,2045.38 ; 960.61,2050.79 cw(c979.76,2044.17) 999.74,2047.53 ; 960.63,2992.17 960.63,2204.83 ccw(c980.31,2204.83) 1000,2204.83 1000,2992.17 4645.67,2992.17 cw(c4645.67,2913.43) 4724.41,2913.43 4724.41,0.05 cw(c4645.67,0.05) 4645.67,-78.69 999.61,-78.69 999.61,103 ; 1000,1754.79 1000,2043.83 ; 1000,1755.79 1000,2042.79 ; 960.63,2045.38 cw(c980.31,2045.38) 1000,2045.38 1000,1756.79 cw(c980.31,1756.79) 960.63,1756.79 960.63,2045.38
  lines w40: 980,217 980,687 ; 980,810 980,1280 ; 980,1392 980,1416 ; 980,1494 980,1671 ; 980,1758 980,2046

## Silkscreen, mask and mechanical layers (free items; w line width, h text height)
Top Overlay:
  lines w5: 1326,1490 1326,1675 1351,1700 1351,1840 ; 1540,897.57 1995.21,897.57 1995.21,1887 1540,1887 1540,897.57
  lines w10: 896,1570 896,1482 896,1413 906,1403 906,1275 ; 1099.6,592.9 3395.6,592.9 ; 1099.6,2340.68 3395.6,2340.68 ; 1099.6,2972.9 3395.6,2972.9 ; 1099.61,376.79 1099.61,592.9 ; 1099.61,2340.68 1099.61,2556.79 ; 1099.61,2756.79 1099.61,2972.9 ; 1102.61,176.79 1102.61,-39.32 3398.61,-39.32 ; 1199.43,375.79 1199.43,591.9 ; 1199.43,2339.68 1199.43,2555.79 ; 1199.43,2755.79 1199.43,2971.9 ; 1202.43,-40.32 1202.43,175.79 ; 1299.26,375.79 1299.26,591.9 ; 1299.26,2339.68 1299.26,2555.79 ; 1299.26,2755.79 1299.26,2971.9 ; 1302.26,-40.32 1302.26,175.79 ; 1399.08,375.79 1399.08,591.9 ; 1399.08,2339.68 1399.08,2555.79 ; 1399.08,2755.79 1399.08,2971.9 ; 1402.09,-40.32 1402.09,175.79 ; 1498.91,375.79 1498.91,591.9 ; 1498.91,2339.68 1498.91,2555.79 ; 1498.91,2755.79 1498.91,2971.9 ; 1501.91,-40.32 1501.91,175.79 ; 1598.74,375.79 1598.74,591.9 ; 1598.74,2339.68 1598.74,2555.79 ; 1598.74,2755.79 1598.74,2971.9 ; 1601.74,-40.32 1601.74,175.79 ; 1698.56,375.79 1698.56,591.9 ; 1698.56,2339.68 1698.56,2555.79 ; 1698.56,2755.79 1698.56,2971.9 ; 1701.56,-40.32 1701.56,175.79 ; 1798.39,375.79 1798.39,591.9 ; 1798.39,2339.68 1798.39,2555.79 ; 1798.39,2755.79 1798.39,2971.9 ; 1801.39,-40.32 1801.39,175.79 ; 1898.21,375.79 1898.21,591.9 ; 1898.21,2339.68 1898.21,2555.79 ; 1898.21,2755.79 1898.21,2971.9 ; 1901.22,-40.32 1901.22,175.79 ; 1998.04,375.79 1998.04,591.9 ; 1998.04,2339.68 1998.04,2555.79 ; 1998.04,2755.79 1998.04,2971.9 ; 2001.04,-40.32 2001.04,175.79 ; 2097.87,375.79 2097.87,591.9 ; 2097.87,2339.68 2097.87,2555.79 ; 2097.87,2755.79 2097.87,2971.9 ; 2100.87,-40.32 2100.87,175.79 ; 2197.69,375.79 2197.69,591.9 ; 2197.69,2339.68 2197.69,2555.79 ; 2197.69,2755.79 2197.69,2971.9 ; 2200.69,-40.32 2200.69,175.79 ; 2297.52,375.79 2297.52,591.9 ; 2297.52,2339.68 2297.52,2555.79 ; 2297.52,2755.79 2297.52,2971.9 ; 2300.52,-40.32 2300.52,175.79 ; 2397.34,375.79 2397.34,591.9 ; 2397.34,2339.68 2397.34,2555.79 ; 2397.34,2755.79 2397.34,2971.9 ; 2400.35,-40.32 2400.35,175.79 ; 2497.17,375.79 2497.17,591.9 ; 2497.17,2339.68 2497.17,2555.79 ; 2497.17,2755.79 2497.17,2971.9 ; 2500.17,-40.32 2500.17,175.79 ; 2597,375.79 2597,591.9 ; 2597,2339.68 2597,2555.79 ; 2597,2755.79 2597,2971.9 ; 2600,-40.32 2600,175.79 ; 2696.82,375.79 2696.82,591.9 ; 2696.82,2339.68 2696.82,2555.79 ; 2696.82,2755.79 2696.82,2971.9 ; 2699.82,-40.32 2699.82,175.79 ; 2796.65,375.79 2796.65,591.9 ; 2796.65,2339.68 2796.65,2555.79 ; 2796.65,2755.79 2796.65,2971.9 ; 2799.65,-40.32 2799.65,175.79 ; 2896.47,375.79 2896.47,591.9 ; 2896.47,2339.68 2896.47,2555.79 ; 2896.47,2755.79 2896.47,2971.9 ; 2899.48,-40.32 2899.48,175.79 ; 2996.3,375.79 2996.3,591.9 ; 2996.3,2339.68 2996.3,2555.79 ; 2996.3,2755.79 2996.3,2971.9 ; 2999.3,-40.32 2999.3,175.79 ; 3096.13,375.79 3096.13,591.9 ; 3096.13,2339.68 3096.13,2555.79 ; 3096.13,2755.79 3096.13,2971.9 ; 3099.13,-40.32 3099.13,175.79 ; 3195.95,375.79 3195.95,591.9 ; 3195.95,2339.68 3195.95,2555.79 ; 3195.95,2755.79 3195.95,2971.9 ; 3198.95,-40.32 3198.95,175.79 ; 3295.78,375.79 3295.78,591.9 ; 3295.78,2339.68 3295.78,2555.79 ; 3295.78,2755.79 3295.78,2971.9 ; 3298.78,-40.32 3298.78,175.79 ; 3395.6,375.79 3395.6,591.9 ; 3395.6,2339.68 3395.6,2555.79 ; 3395.6,2755.79 3395.6,2971.9 ; 3398.61,-40.32 3398.61,175.79
  text "PC4" at 2322.61,2950.79 h51.18 r270
  text "PB6" at 2522.61,2950.79 h51.18 r270
  text "PB15" at 2722.61,2950.79 h51.18 r270
  text "PB12" at 2922.61,2950.79 h51.18 r270
  text "PE1" at 1122.61,2949.79 h51.18 r270
  text "PD15" at 1222.61,2949.79 h51.18 r270
  text "PD11" at 1322.61,2950.31 h51.18 r270
  text "PD13" at 1422.61,2950.31 h51.18 r270
  text "PC8" at 1522.61,2949.79 h51.18 r270
  text "PC6" at 1622.61,2949.79 h51.18 r270
  text "PC7" at 1722.61,2949.79 h51.18 r270
  text "GND" at 1822.61,2949.79 h51.18 r270
  text "5V0" at 1921.61,2950.31 h51.18 r270
  text "PC0" at 2022.61,2949.79 h51.18 r270
  text "PC1" at 2122.61,2949.79 h51.18 r270
  text "PC3" at 2222.61,2949.79 h51.18 r270
  text "GND" at 2422.61,2949.79 h51.18 r270
  text "PB2" at 2622.61,2949.79 h51.18 r270
  text "PB13" at 2822.61,2949.79 h51.18 r270
  text "GND" at 3022.61,2949.79 h51.18 r270
  text "PA0" at 3122.61,2949.79 h51.18 r270
  text "VLCD" at 3222.61,2949.79 h51.18 r270
  text "GND" at 3322.61,2949.79 h51.18 r270
  text "CMSIS-DAP" at 38,2709 h51.18 r270
  text "PE0" at 1123.89,2524.55 h51.18 r270
  text "PD14" at 1223.89,2524.55 h51.18 r270
  text "PD10" at 1323.89,2524.55 h51.18 r270
  text "PD12" at 1423.89,2524.55 h51.18 r270
  text "PC9" at 1523.89,2524.55 h51.18 r270
  text "PB8" at 1623.89,2524.55 h51.18 r270
  text "PB9" at 1723.89,2524.55 h51.18 r270
  text "GND" at 1923.89,2525.07 h51.18 r270
  text "PA5" at 2023.89,2524.55 h51.18 r270
  text "PA6" at 2123.89,2524.55 h51.18 r270
  text "PA7" at 2223.89,2524.55 h51.18 r270
  text "PB0" at 2323.89,2524.55 h51.18 r270
  text "PB1" at 2423.89,2524.55 h51.18 r270
  text "PA9" at 2523.89,2524.55 h51.18 r270
  text "PA8" at 2623.89,2525.07 h51.18 r270
  text "PB14" at 2723.89,2524.55 h51.18 r270
  text "PB5" at 2823.89,2524.55 h51.18 r270
  text "PB4" at 2923.89,2524.55 h51.18 r270
  text "PB3" at 3023.89,2524.55 h51.18 r270
  text "PA10" at 3123.89,2524.55 h51.18 r270
  text "PA11" at 3223.89,2525.07 h51.18 r270
  text "PA12" at 3321.89,2524.55 h51.18 r270
  text "NC" at 1823,2498 h51.18 r270
  text "USER" at 1878,2218 h50
  text "LITE-80" at 2677,2191 h60 r270
  text "HB1020C" at 2757,2191 h60 r270
  text "PwrTest" at 1934,2155 h50 r270
  text "BOOT0" at 1135.02,1861 h50
  text "VDD" at 1138,1625 h50
  text "GND" at 1138,1534 h50
  text "SWDIO" at 1134,1430 h50
  text "SWCLK" at 1134,1335 h50
  text "NRST" at 1134,1228 h50
  text "RESET" at 1599.02,749 h50
  text "PE3" at 1122.85,569.03 h51.18 r270
  text "Vcore" at 1728,569 h51.18 r270
  text "GND" at 2425.61,562.79 h51.18 r270
  text "GND" at 2525.61,562.79 h51.18 r270
  text "PD5" at 2725.61,562.79 h51.18 r270
  text "PA2" at 2925.61,562.79 h51.18 r270
  text "PA3" at 3025.61,562.79 h51.18 r270
  text "PA4" at 3125.61,562.79 h51.18 r270
  text "PB10" at 3225.61,562.79 h51.18 r270
  text "PB11" at 3325.61,562.79 h51.18 r270
  text "VLDO" at 2225.61,562.31 h51.18 r270
  text "PA1" at 2825.61,562.31 h51.18 r270
  text "PE5" at 1225.61,561.33 h51.18 r270
  text "PD7" at 1325.61,561.33 h51.18 r270
  text "PD9" at 1425.61,561.33 h51.18 r270
  text "PD2" at 1525.61,561.33 h51.18 r270
  text "PC11" at 1626.61,561.33 h51.18 r270
  text "PA14" at 1825.61,561.33 h51.18 r270
  text "PA15" at 1925.61,561.33 h51.18 r270
  text "VLDO" at 2025.61,561.31 h51.18 r270
  text "NRST" at 2125.61,561.33 h51.18 r270
  text "NC" at 2321,540 h51.18 r270
  text "NC" at 2623.95,539.05 h51.18 r270
  text "NRST" at 691,352 h50 r270
  text "SCLK" at 587,348 h50 r270
  text "SDIO" at 487,320 h50 r270
  text "VCC" at 290,315 h50 r270
  text "GND" at 389,314 h50 r270
  text "PE4" at 1227.78,137.79 h51.18 r270
  text "PD6" at 1327.78,137.79 h51.18 r270
  text "PC12" at 1527.78,137.79 h51.18 r270
  text "VDD" at 1727.78,137.79 h51.18 r270
  text "PA13" at 1827.78,137.79 h51.18 r270
  text "GND" at 1927.78,137.79 h51.18 r270
  text "PD0" at 2127.78,137.79 h51.18 r270
  text "PD3" at 2227.78,137.79 h51.18 r270
  text "PD4" at 2327.78,137.79 h51.18 r270
  text "GND" at 2427.78,137.79 h51.18 r270
  text "PB7" at 2527.78,137.79 h51.18 r270
  text "PC13" at 2627.78,137.79 h51.18 r270
  text "PC15" at 2727.78,137.79 h51.18 r270
  text "PF1" at 2927.78,137.79 h51.18 r270
  text "PF0" at 3027.78,137.79 h51.18 r270
  text "VBAT" at 3127.78,137.79 h51.18 r270
  text "PC5" at 3327.78,137.79 h51.18 r270
  text "PE2" at 1127.78,137.31 h51.18 r270
  text "PD8" at 1427.78,137.31 h51.18 r270
  text "PC10" at 1627.78,137.31 h51.18 r270
  text "PD1" at 2027.78,137.31 h51.18 r270
  text "PC14" at 2827.78,137.31 h51.18 r270
  text "PC2" at 3227.78,137.31 h51.18 r270

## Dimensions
0,2913.43 to 4724.41,0.05 on Mechanical 13
999.61,-78.69 to 1000,2992.17 on Mechanical 13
